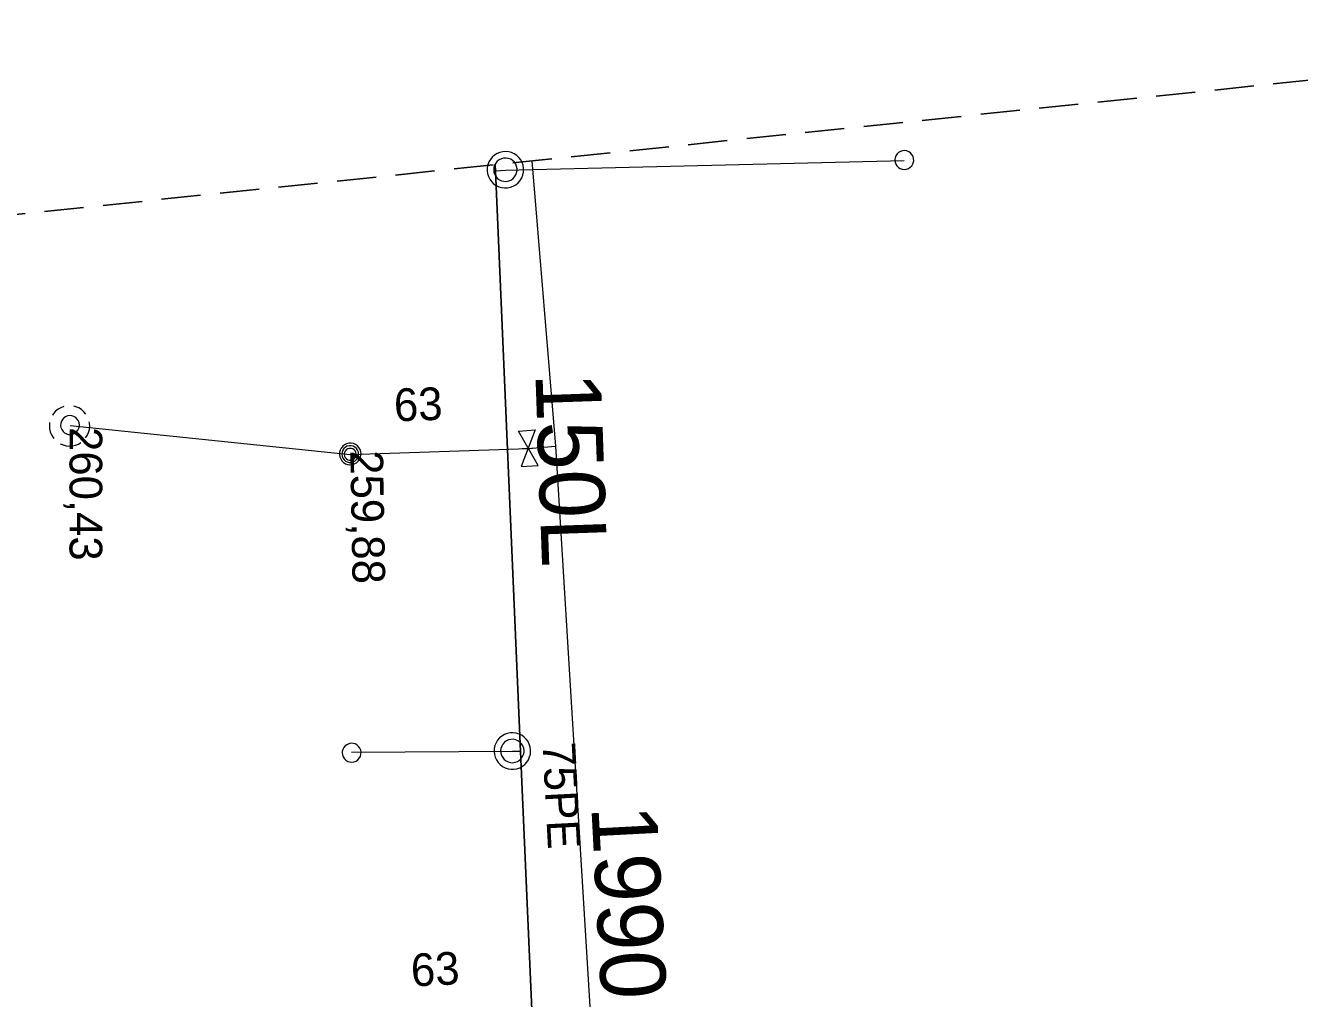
# Model space of a CAD drawing. Extents: x -732096 to -731933, y -1048703 to -1047964.
# Drawn here: x -732046.17 to -732014.98, y -1047987.86 to -1047964.04 of the extents above; entities that cross this region are included whole.
import ezdxf

# ---------------------------------------------------------------- set-up
doc = ezdxf.new("R2010")
doc.units = 0
doc.header["$LTSCALE"] = 0.32
doc.linetypes.add('MEDIUM_DASHED', pattern=[4.5, 3, -1.5])
doc.layers.add('1', color=7, linetype='Continuous')
for name, color, linetype, lineweight in [('18', 7, 'Continuous', 13), ('21', 7, 'Continuous', 13), ('50', 7, 'Continuous', 13), ('63', 7, 'MEDIUM_DASHED', 25), ('8', 7, 'Continuous', 13)]:
    doc.layers.add(name, color=color, linetype=linetype, lineweight=lineweight)

msp = doc.modelspace()

# ---------------------------------------------------------------- linework, layer by layer
at = {"layer": '18'}
for q in [(-732034.011, -1047974.4), (-732033.712, -1047974.377)]:
    msp.add_line((-732033.861, -1047974.389), q, dxfattribs=at)
for points in [[(-732045.232, -1047973.367), (-732045.303, -1047973.395), (-732045.37, -1047973.434), (-732045.43, -1047973.482), (-732045.481, -1047973.539), (-732045.505, -1047973.573)], [(-732044.691, -1047973.55), (-732044.741, -1047973.492), (-732044.799, -1047973.442), (-732044.864, -1047973.401), (-732044.935, -1047973.372), (-732044.984, -1047973.358)], [(-732045.577, -1047973.759), (-732045.583, -1047973.836), (-732045.578, -1047973.913), (-732045.561, -1047973.988), (-732045.532, -1047974.059), (-732045.492, -1047974.125), (-732045.476, -1047974.147)], [(-732044.696, -1047974.136), (-732044.655, -1047974.071), (-732044.624, -1047974.001), (-732044.605, -1047973.926), (-732044.597, -1047973.85), (-732044.602, -1047973.773), (-732044.608, -1047973.738)], [(-732045.319, -1047974.276), (-732045.249, -1047974.307), (-732045.174, -1047974.326), (-732045.098, -1047974.333), (-732045.021, -1047974.328), (-732044.946, -1047974.311), (-732044.874, -1047974.283), (-732044.814, -1047974.248)]]:
    msp.add_lwpolyline(points, dxfattribs=at)
for points in [[(-732044.848, -1047973.819), (-732044.854, -1047973.767), (-732044.872, -1047973.717), (-732044.9, -1047973.673), (-732044.938, -1047973.636), (-732044.983, -1047973.609), (-732045.033, -1047973.593), (-732045.085, -1047973.588), (-732045.137, -1047973.595), (-732045.186, -1047973.614), (-732045.23, -1047973.644), (-732045.265, -1047973.683), (-732045.291, -1047973.728), (-732045.306, -1047973.779), (-732045.309, -1047973.831), (-732045.301, -1047973.883), (-732045.28, -1047973.931), (-732045.25, -1047973.974), (-732045.21, -1047974.009), (-732045.164, -1047974.033), (-732045.113, -1047974.047), (-732045.061, -1047974.049), (-732045.009, -1047974.039), (-732044.961, -1047974.017), (-732044.919, -1047973.985), (-732044.886, -1047973.945), (-732044.862, -1047973.898), (-732044.85, -1047973.847)], [(-732033.622, -1047974.806), (-732034.101, -1047973.972), (-732033.688, -1047973.94), (-732034.034, -1047974.837)], [(-732037.955, -1047974.527), (-732037.961, -1047974.471), (-732037.978, -1047974.418), (-732038.007, -1047974.369), (-732038.045, -1047974.328), (-732038.091, -1047974.296), (-732038.143, -1047974.274), (-732038.198, -1047974.263), (-732038.254, -1047974.265), (-732038.309, -1047974.278), (-732038.36, -1047974.303), (-732038.404, -1047974.338), (-732038.44, -1047974.381), (-732038.465, -1047974.431), (-732038.48, -1047974.486), (-732038.483, -1047974.542), (-732038.474, -1047974.597), (-732038.453, -1047974.65), (-732038.422, -1047974.696), (-732038.382, -1047974.735), (-732038.334, -1047974.765), (-732038.281, -1047974.784), (-732038.225, -1047974.791), (-732038.169, -1047974.787), (-732038.115, -1047974.77), (-732038.066, -1047974.743), (-732038.024, -1047974.705), (-732037.991, -1047974.66), (-732037.968, -1047974.609), (-732037.956, -1047974.554)], [(-732038.014, -1047974.53), (-732038.02, -1047974.481), (-732038.038, -1047974.435), (-732038.066, -1047974.394), (-732038.103, -1047974.361), (-732038.147, -1047974.339), (-732038.195, -1047974.327), (-732038.244, -1047974.327), (-732038.292, -1047974.339), (-732038.336, -1047974.362), (-732038.373, -1047974.395), (-732038.401, -1047974.436), (-732038.418, -1047974.483), (-732038.424, -1047974.532), (-732038.417, -1047974.581), (-732038.399, -1047974.627), (-732038.371, -1047974.667), (-732038.334, -1047974.7), (-732038.29, -1047974.722), (-732038.241, -1047974.734), (-732038.192, -1047974.733), (-732038.144, -1047974.721), (-732038.101, -1047974.697), (-732038.064, -1047974.664), (-732038.036, -1047974.623), (-732038.02, -1047974.576)], [(-732038.073, -1047974.534), (-732038.079, -1047974.492), (-732038.096, -1047974.454), (-732038.124, -1047974.423), (-732038.159, -1047974.4), (-732038.199, -1047974.389), (-732038.241, -1047974.389), (-732038.281, -1047974.401), (-732038.316, -1047974.424), (-732038.343, -1047974.456), (-732038.36, -1047974.494), (-732038.365, -1047974.535), (-732038.359, -1047974.577), (-732038.341, -1047974.614), (-732038.313, -1047974.646), (-732038.277, -1047974.668), (-732038.237, -1047974.679), (-732038.195, -1047974.678), (-732038.155, -1047974.665), (-732038.121, -1047974.642), (-732038.094, -1047974.609), (-732038.078, -1047974.571)]]:
    msp.add_lwpolyline(points, close=True, dxfattribs=at)
at = {"layer": '21'}
msp.add_lwpolyline([(-732033.777, -1047967.353), (-732033.19, -1047974.34), (-732032.34, -1047988.32), (-732031.48, -1047999.87)], dxfattribs=at)
msp.add_lwpolyline([(-732033.777, -1047967.353), (-732033.19, -1047974.34), (-732032.34, -1047988.32), (-732031.48, -1047999.87)], dxfattribs=at)
at = {"layer": '50'}
for p, q in [((-732045.079, -1047973.83), (-732038.219, -1047974.54)), ((-732038.219, -1047974.54), (-732033.859, -1047974.39)), ((-732033.859, -1047974.39), (-732033.19, -1047974.34))]:
    msp.add_line(p, q, dxfattribs=at)
msp.add_lwpolyline([(-732045.079, -1047973.83), (-732038.219, -1047974.54), (-732033.859, -1047974.39), (-732033.19, -1047974.34)], dxfattribs=at)
at = {"layer": '63'}
msp.add_lwpolyline([(-732040.436, -1048145.923), (-732073.567, -1048047.117), (-732073.568, -1048047.115), (-732073.568, -1048047.114), (-732073.568, -1048047.112), (-732060.033, -1047970.086), (-732060.033, -1047970.084), (-732060.032, -1047970.082), (-732060.031, -1047970.081), (-732060.029, -1047970.079), (-732060.028, -1047970.078), (-732060.026, -1047970.078), (-732060.024, -1047970.077), (-732001.831, -1047964.038), (-732001.829, -1047964.038), (-732001.827, -1047964.038), (-732001.825, -1047964.039), (-732001.823, -1047964.04), (-732001.822, -1047964.041), (-732001.821, -1047964.043), (-732001.82, -1047964.045), (-732001.82, -1047964.047), (-731997.077, -1048043.55), (-731968.389, -1048129.387)], dxfattribs=at)
at = {"layer": '8'}
for p, q in [((-732034.659, -1047967.6), (-732034.42, -1047967.58)), ((-732034.42, -1047967.58), (-732024.657, -1047967.343)), ((-732034.25, -1047981.81), (-732038.184, -1047981.831)), ((-732034.05, -1047981.809), (-732034.25, -1047981.81))]:
    msp.add_line(p, q, dxfattribs=at)
for points in [[(-732033.975, -1047967.533), (-732033.987, -1047967.461), (-732034.01, -1047967.392), (-732034.044, -1047967.327), (-732034.089, -1047967.27), (-732034.142, -1047967.219), (-732034.203, -1047967.178), (-732034.269, -1047967.149), (-732034.34, -1047967.129), (-732034.413, -1047967.122), (-732034.487, -1047967.127), (-732034.558, -1047967.144), (-732034.626, -1047967.172), (-732034.687, -1047967.21), (-732034.742, -1047967.259), (-732034.789, -1047967.316), (-732034.825, -1047967.379), (-732034.85, -1047967.448), (-732034.865, -1047967.519), (-732034.867, -1047967.593), (-732034.857, -1047967.665), (-732034.835, -1047967.735), (-732034.803, -1047967.8), (-732034.76, -1047967.86), (-732034.708, -1047967.911), (-732034.648, -1047967.953), (-732034.583, -1047967.985), (-732034.513, -1047968.007), (-732034.44, -1047968.016), (-732034.367, -1047968.013), (-732034.295, -1047967.998), (-732034.227, -1047967.972), (-732034.163, -1047967.935), (-732034.107, -1047967.888), (-732034.059, -1047967.833), (-732034.021, -1047967.77), (-732033.993, -1047967.702), (-732033.978, -1047967.631), (-732033.974, -1047967.558)], [(-732034.135, -1047967.546), (-732034.146, -1047967.489), (-732034.168, -1047967.434), (-732034.2, -1047967.386), (-732034.243, -1047967.345), (-732034.291, -1047967.313), (-732034.346, -1047967.292), (-732034.404, -1047967.283), (-732034.463, -1047967.286), (-732034.519, -1047967.3), (-732034.572, -1047967.326), (-732034.619, -1047967.362), (-732034.656, -1047967.406), (-732034.684, -1047967.458), (-732034.702, -1047967.514), (-732034.707, -1047967.572), (-732034.7, -1047967.631), (-732034.682, -1047967.686), (-732034.653, -1047967.737), (-732034.613, -1047967.78), (-732034.566, -1047967.815), (-732034.513, -1047967.839), (-732034.456, -1047967.853), (-732034.397, -1047967.854), (-732034.34, -1047967.844), (-732034.286, -1047967.822), (-732034.237, -1047967.789), (-732034.196, -1047967.747), (-732034.165, -1047967.698), (-732034.145, -1047967.643), (-732034.135, -1047967.585)], [(-732024.425, -1047967.348), (-732024.428, -1047967.296), (-732024.442, -1047967.245), (-732024.467, -1047967.199), (-732024.502, -1047967.159), (-732024.545, -1047967.129), (-732024.594, -1047967.11), (-732024.646, -1047967.101), (-732024.698, -1047967.105), (-732024.748, -1047967.12), (-732024.794, -1047967.147), (-732024.832, -1047967.183), (-732024.861, -1047967.226), (-732024.879, -1047967.276), (-732024.886, -1047967.328), (-732024.882, -1047967.38), (-732024.864, -1047967.43), (-732024.837, -1047967.475), (-732024.8, -1047967.512), (-732024.755, -1047967.54), (-732024.706, -1047967.557), (-732024.654, -1047967.563), (-732024.601, -1047967.556), (-732024.552, -1047967.538), (-732024.508, -1047967.509), (-732024.472, -1047967.471), (-732024.445, -1047967.426), (-732024.429, -1047967.376)], [(-732033.804, -1047981.776), (-732033.813, -1047981.703), (-732033.835, -1047981.633), (-732033.867, -1047981.568), (-732033.91, -1047981.509), (-732033.962, -1047981.456), (-732034.021, -1047981.414), (-732034.087, -1047981.382), (-732034.157, -1047981.361), (-732034.229, -1047981.351), (-732034.303, -1047981.354), (-732034.375, -1047981.369), (-732034.443, -1047981.395), (-732034.506, -1047981.431), (-732034.562, -1047981.478), (-732034.611, -1047981.534), (-732034.649, -1047981.596), (-732034.676, -1047981.664), (-732034.693, -1047981.735), (-732034.697, -1047981.808), (-732034.689, -1047981.881), (-732034.67, -1047981.951), (-732034.64, -1047982.018), (-732034.598, -1047982.079), (-732034.548, -1047982.131), (-732034.489, -1047982.175), (-732034.425, -1047982.209), (-732034.355, -1047982.233), (-732034.283, -1047982.244), (-732034.21, -1047982.244), (-732034.137, -1047982.231), (-732034.068, -1047982.206), (-732034.004, -1047982.171), (-732033.946, -1047982.126), (-732033.897, -1047982.073), (-732033.857, -1047982.011), (-732033.827, -1047981.944), (-732033.81, -1047981.873), (-732033.803, -1047981.801)], [(-732038.414, -1047981.841), (-732038.408, -1047981.893), (-732038.39, -1047981.943), (-732038.362, -1047981.987), (-732038.323, -1047982.024), (-732038.278, -1047982.051), (-732038.228, -1047982.066), (-732038.176, -1047982.071), (-732038.124, -1047982.064), (-732038.075, -1047982.044), (-732038.031, -1047982.014), (-732037.997, -1047981.975), (-732037.971, -1047981.93), (-732037.956, -1047981.879), (-732037.954, -1047981.827), (-732037.962, -1047981.775), (-732037.983, -1047981.727), (-732038.013, -1047981.684), (-732038.054, -1047981.649), (-732038.1, -1047981.626), (-732038.151, -1047981.612), (-732038.203, -1047981.61), (-732038.255, -1047981.62), (-732038.303, -1047981.643), (-732038.344, -1047981.675), (-732038.377, -1047981.715), (-732038.401, -1047981.762), (-732038.413, -1047981.813)], [(-732033.964, -1047981.784), (-732033.973, -1047981.726), (-732033.994, -1047981.671), (-732034.025, -1047981.622), (-732034.066, -1047981.58), (-732034.113, -1047981.546), (-732034.168, -1047981.524), (-732034.225, -1047981.512), (-732034.284, -1047981.513), (-732034.341, -1047981.526), (-732034.395, -1047981.551), (-732034.442, -1047981.585), (-732034.481, -1047981.628), (-732034.51, -1047981.679), (-732034.53, -1047981.735), (-732034.537, -1047981.792), (-732034.532, -1047981.851), (-732034.515, -1047981.907), (-732034.487, -1047981.959), (-732034.449, -1047982.003), (-732034.403, -1047982.04), (-732034.351, -1047982.065), (-732034.294, -1047982.081), (-732034.236, -1047982.084), (-732034.178, -1047982.075), (-732034.123, -1047982.055), (-732034.074, -1047982.023), (-732034.032, -1047981.982), (-732033.999, -1047981.935), (-732033.977, -1047981.88), (-732033.965, -1047981.823)]]:
    msp.add_lwpolyline(points, close=True, dxfattribs=at)
at = {"layer": '8', "lineweight": 25}
msp.add_lwpolyline([(-732034.674, -1047967.446), (-732034.659, -1047967.6), (-732034.05, -1047981.809), (-732033.525, -1047993.715), (-732033.46, -1047995.21)], dxfattribs=at)

# ---------------------------------------------------------------- texts
at = {"layer": '1'}
for s, height, rotation, p in [('63', 0.8, 2, (-732037.136, -1047973.73)), ('150L', 1.6, 272, (-732033.687, -1047972.555)), ('260,43', 0.8, 270, (-732045.09, -1047973.867)), ('259,88', 0.8, 271, (-732038.218, -1047974.443)), ('75PE', 0.8, 273, (-732033.513, -1047981.603)), ('1990', 1.6, 273, (-732032.317, -1047983.159)), ('63', 0.8, 3, (-732036.714, -1047987.566))]:
    msp.add_text(s, height=height, rotation=rotation, dxfattribs=at).set_placement(p)

doc.saveas('drawing.dxf')
